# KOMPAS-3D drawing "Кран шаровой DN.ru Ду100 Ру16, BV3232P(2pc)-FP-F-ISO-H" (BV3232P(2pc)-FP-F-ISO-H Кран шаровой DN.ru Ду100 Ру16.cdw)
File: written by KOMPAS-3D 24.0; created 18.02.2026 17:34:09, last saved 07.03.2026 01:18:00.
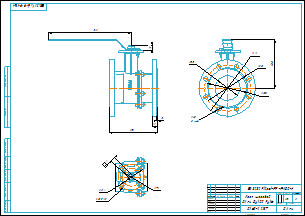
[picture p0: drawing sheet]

Document properties: Автор: R2D2; Форматы листов документа: A2; Полное имя файла: BV3232P(2pc)-FP-F-ISO-H Кран шаровой DN.ru Ду100 Ру16.m3d; Масса: 19.2; Наименование: Кран шаровой DN.ru Ду100 Ру16; Количество листов документа: 1; Примечание: D160-22137

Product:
- Component [detail]: Сборка  | qty 1  | pos. 1  | source file: исходные материалы\1.m3d
- Component [detail]: Сборка  | qty 1  | pos. 1  | Масса: 0.506937; Автор: R2D2; source file: исходные материалы\2.m3d
- Part/product: Кран шаровой DN.ru Ду100 Ру16  | designation BV3232P(2pc)-FP-F-ISO-H
    Масса: 19.2
    Раздел спецификации: Прочие изделия
    Примечание: D160-22137

Views: Проекционный вид 2
Referenced files in E:\Работа\Зайцев\BV3232P(2pc)-FP-F-ISO-H Кран шаровой DN.ru Ду15-300 Ру16-40\DN100 PN16\: BV3232P(2pc)-FP-F-ISO-H Кран шаровой DN.ru Ду100 Ру16.m3d
Referenced files in E:\Работа\Зайцев\Для компаса\: чертеж DN.ru А3.cdt
Referenced files in E:\Работа\Зайцев\BV3232P(2pc)-FP-F-ISO-H Кран шаровой DN.ru Ду15-300 Ру16-40\DN100 PN16\исходные материалы\: 1.m3d, Деталь1 Деталь1.m3d, Деталь2 Деталь2.m3d, Деталь3 Деталь3.m3d, Деталь5 Деталь5.m3d, Деталь6 Деталь6.m3d, Деталь7 Деталь7.m3d, AS 1421 - M10 x 35 засверленный конец AS 1421 - M10 x 35 засверленный конец.m3d, AS 1420 - 1973 - M8 x 30 AS 1420 - 1973 - M8 x 30.m3d, ANSI B18.2.4.2M - M10x1,5 ANSI B18.2.4.2M - M10x1,5 - 16.m3d, ANSI B18.2.4.2M - M8x1,25 ANSI B18.2.4.2M - M8x1,25 - 13.m3d, BS 3692 - M12 BS 3692 - M12(4).m3d, 2.m3d
Referenced files in C:\Program Files\ASCON\KOMPAS-3D v24\Libs\PolynomLib\DATA\vault\Methods\Kompas\3D\: PLib_Nut_OST92_900.m3d
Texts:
  BV3232P(2pc)-FP-F-ISO-H
  чертеж DN.ru А3.cdt
  Кран шаровой
  DN.ru Ду100 Ру16
  Твердое тело1
  Деталь1
  Деталь1 Деталь1
  Деталь2
  Деталь2 Деталь2
  Деталь3
  Деталь3 Деталь3
  Деталь5
  Деталь5 Деталь5
  Деталь6
  Деталь6 Деталь6
  Деталь7
  Деталь7 Деталь7
  Solid1
  AS 1421 - M10 x 35 засверленный конец
  AS 1421 - M10 x 35 засверленный   конец
  AS 1421 - M10 x 35 засверленный   конец AS 1421 - M10 x 35 засверленный конец
  AS 1420 - 1973 - M8 x 30
  AS 1420 - 1973 - M8 x 30 AS 1420 - 1973 - M8 x 30
  ANSI B18.2.4.2M - M10x1,5 - 16
  ANSI B18.2.4.2M - M10x1,5
  ANSI B18.2.4.2M - M10x1,5 ANSI B18.2.4.2M - M10x1,5 - 16
  ANSI B18.2.4.2M - M8x1,25 - 13
  ANSI B18.2.4.2M - M8x1,25
  ANSI B18.2.4.2M - M8x1,25 ANSI B18.2.4.2M - M8x1,25 - 13
  BS 3692 - M12(4)
  BS 3692 - M12
  BS 3692 - M12 BS 3692 - M12(4)
  Сборка
  Сборка Сборка
  Гайка М20-6H ГОСТ 5916-70
  Кран шаровой DN.ru Ду100 Ру16
  BV3232P(2pc)-FP-F-ISO-H Кран шаровой DN.ru Ду100 Ру16
Dimensions and other numbers on the sheet: 0; 3; 4; 220; 180; 158; 99; 18; 8 отв.; 188; 1:2; 1; 2; 19,2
